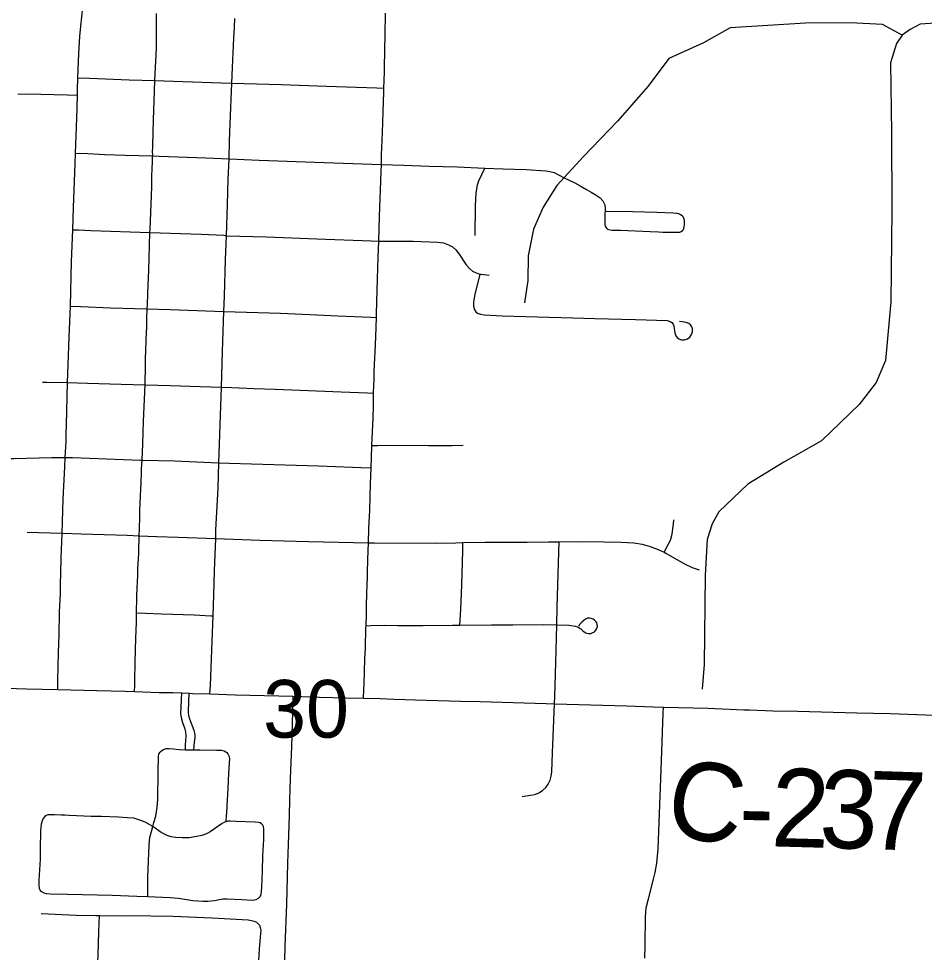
# Model space of a CAD drawing. Extents: x -59 to 43, y 0 to 22.
# Drawn here: x 25.512 to 26.169, y 16.594 to 17.272 of the extents above; entities that cross this region are included whole.
import ezdxf

# ---------------------------------------------------------------- set-up
doc = ezdxf.new("R2010")
doc.units = 0
for name, color, linetype in [('GM_X_City_Street', 7, 'Continuous'), ('GM_X_County_Road', 7, 'Continuous'), ('GM_X_County_Road_Text', 7, 'Continuous'), ('GM_X_Minor_River', 7, 'Continuous'), ('GM_X_Section_Text', 7, 'Continuous')]:
    doc.layers.add(name, color=color, linetype=linetype)

msp = doc.modelspace()

# ---------------------------------------------------------------- linework, layer by layer
at = {"layer": 'GM_X_City_Street'}
msp.add_line((25.63317, 16.74104), (25.63944, 16.74115), dxfattribs=at)
for points in [[(25.59632, 16.78345), (25.59641, 16.78792), (25.59649, 16.79187), (25.59673, 16.80396), (25.59705, 16.81375), (25.59719, 16.82198), (25.59771, 16.83378), (25.59776, 16.83691), (25.59772, 16.83937), (25.59772, 16.84054), (25.59772, 16.84306), (25.59777, 16.84429), (25.59787, 16.84799), (25.59805, 16.85414), (25.59819, 16.85721), (25.59849, 16.86457), (25.59862, 16.86644), (25.59861, 16.86763), (25.59877, 16.87243), (25.59887, 16.87656), (25.59916, 16.87988), (25.59933, 16.88358), (25.59947, 16.88863), (25.59954, 16.89323), (25.59964, 16.89656), (25.59979, 16.90185), (25.59982, 16.90251), (25.60003, 16.90923), (25.6002, 16.91477), (25.60035, 16.91968), (25.60074, 16.92585), (25.60086, 16.93018), (25.60102, 16.93513), (25.60128, 16.94196), (25.60141, 16.94443), (25.60157, 16.94878), (25.60172, 16.95138), (25.60241, 16.96328), (25.6029, 16.97973), (25.60395, 17.0062), (25.60404, 17.00827), (25.60428, 17.01823), (25.60436, 17.02588), (25.60443, 17.03016), (25.60477, 17.0392), (25.60501, 17.04347), (25.60515, 17.04853), (25.60525, 17.05162), (25.60532, 17.05407), (25.60551, 17.06136), (25.6056, 17.06459), (25.60615, 17.07868), (25.60663, 17.08921), (25.60746, 17.11679), (25.60753, 17.11914), (25.60801, 17.13115), (25.60875, 17.14983), (25.60891, 17.15789), (25.60907, 17.16274), (25.60923, 17.16825), (25.60944, 17.17231), (25.60948, 17.17298), (25.60943, 17.17545), (25.60947, 17.17837), (25.60953, 17.18241), (25.60973, 17.18654), (25.60985, 17.18956), (25.61036, 17.20626), (25.61054, 17.21183), (25.61114, 17.22693), (25.61216, 17.2505), (25.61218, 17.25585), (25.61231, 17.27567)], [(25.65096, 16.78173), (25.65133, 16.78808), (25.65171, 16.79422), (25.65274, 16.81992), (25.65339, 16.83837), (25.65393, 16.85337), (25.65445, 16.87112), (25.65542, 16.89462), (25.65542, 16.90056), (25.6569, 16.93123), (25.65738, 16.94953), (25.65934, 17.00445), (25.66006, 17.03042), (25.66104, 17.05937), (25.66153, 17.0705), (25.66226, 17.09722), (25.663, 17.11428), (25.66373, 17.13704), (25.66422, 17.1551), (25.66495, 17.17019), (25.6651, 17.18314), (25.66581, 17.19556), (25.66691, 17.22511), (25.6674, 17.23648), (25.66837, 17.25776), (25.66886, 17.26567), (25.66911, 17.27211)], [(25.55517, 17.22901), (25.56372, 17.22868), (25.59245, 17.22754), (25.61114, 17.22693), (25.6313, 17.22627), (25.65908, 17.22538), (25.66691, 17.22511), (25.70271, 17.22406), (25.73567, 17.22291), (25.75744, 17.22217), (25.77204, 17.22169), (25.7773, 17.22151)], [(25.51156, 17.21748), (25.52833, 17.21708), (25.54762, 17.21666), (25.55487, 17.2165)], [(25.55353, 17.1744), (25.56231, 17.17397), (25.57466, 17.17336), (25.58956, 17.17287), (25.60944, 17.17231), (25.61415, 17.17218), (25.64806, 17.17089), (25.66495, 17.17019), (25.68672, 17.16921), (25.73396, 17.1675), (25.77544, 17.1661), (25.79185, 17.16555), (25.81016, 17.16481), (25.83044, 17.16432), (25.85048, 17.16334)], [(25.84352, 17.11441), (25.8438, 17.13597), (25.84436, 17.14518), (25.84526, 17.15127), (25.84613, 17.15424), (25.85048, 17.16334)], [(25.85048, 17.16334), (25.86384, 17.16286), (25.88041, 17.16237), (25.89471, 17.16153), (25.89777, 17.16109), (25.90087, 17.16024), (25.90812, 17.15644), (25.91578, 17.15273), (25.91975, 17.15051), (25.92438, 17.14803), (25.92766, 17.14606), (25.93063, 17.14433), (25.93418, 17.1419), (25.93608, 17.13964), (25.93756, 17.13691), (25.93781, 17.13419), (25.93756, 17.129), (25.93758, 17.12413), (25.93774, 17.12247), (25.93794, 17.12128), (25.93831, 17.12054), (25.93885, 17.11983), (25.93964, 17.11918), (25.94059, 17.11877), (25.9415, 17.11853), (25.94304, 17.11836), (25.94909, 17.11832), (25.97054, 17.11742), (25.97655, 17.11716), (25.97971, 17.11706), (25.98585, 17.11694), (25.99001, 17.1169), (25.99135, 17.11693), (25.99197, 17.11701), (25.99305, 17.11738), (25.994, 17.1181), (25.99462, 17.11894), (25.99491, 17.11954), (25.99524, 17.12078), (25.99545, 17.12232), (25.99556, 17.12384), (25.99549, 17.12528), (25.99524, 17.12643), (25.99478, 17.1275), (25.99439, 17.12803), (25.99396, 17.12853), (25.99303, 17.12927), (25.99251, 17.12964), (25.99181, 17.13003), (25.99038, 17.13045), (25.98965, 17.13053), (25.98712, 17.13068), (25.97541, 17.13124), (25.9576, 17.13173), (25.93849, 17.13204)], [(25.55146, 17.11873), (25.55541, 17.11857), (25.5647, 17.11819), (25.60746, 17.11679), (25.64457, 17.11558), (25.66112, 17.11482), (25.663, 17.11428), (25.69218, 17.11355), (25.72857, 17.11219), (25.76813, 17.11062), (25.77356, 17.1104)], [(25.77356, 17.1104), (25.79858, 17.11035), (25.81608, 17.10977), (25.82051, 17.10909), (25.82422, 17.10785), (25.82706, 17.10621), (25.82951, 17.10403), (25.83191, 17.10097), (25.83698, 17.09316), (25.83934, 17.09047), (25.84165, 17.08868), (25.84425, 17.08734), (25.84699, 17.08655), (25.84766, 17.08635), (25.85187, 17.08586), (25.85373, 17.08577)], [(25.84699, 17.08655), (25.84537, 17.08043), (25.84316, 17.07205), (25.84223, 17.06604), (25.84228, 17.06315), (25.8429, 17.06101), (25.8441, 17.05919), (25.84529, 17.05816), (25.84731, 17.05735), (25.85012, 17.05703), (25.86312, 17.05632), (25.9144, 17.05481), (25.93039, 17.05425), (25.95991, 17.05355), (25.98293, 17.05273), (25.98497, 17.05215), (25.98624, 17.05135), (25.98723, 17.05015), (25.98776, 17.04875), (25.98833, 17.04378), (25.98907, 17.04171), (25.99002, 17.04042), (25.99127, 17.03945), (25.9933, 17.03877), (25.99547, 17.03879), (25.99751, 17.03951), (25.99928, 17.04083), (26.00056, 17.0426), (26.00125, 17.04467), (26.00124, 17.04682), (26.00072, 17.04831), (25.99978, 17.04961), (25.99853, 17.0506), (25.99658, 17.05148), (25.99372, 17.05195), (25.99191, 17.05204)], [(25.54972, 17.06322), (25.5574, 17.06293), (25.57896, 17.06211), (25.60551, 17.06136), (25.62204, 17.06088), (25.66104, 17.05937), (25.70216, 17.05816), (25.72358, 17.05722), (25.74391, 17.05619), (25.7679, 17.05521), (25.77185, 17.05505)], [(25.52957, 17.0081), (25.53267, 17.00804), (25.54765, 17.0077), (25.56212, 17.00738), (25.58661, 17.00664), (25.60395, 17.0062), (25.62237, 17.00574), (25.64401, 17.0049), (25.65934, 17.00445), (25.66701, 17.00421), (25.68302, 17.00342), (25.69831, 17.0029), (25.71648, 17.00225), (25.74616, 17.00103), (25.76546, 17.00029), (25.76984, 17.00013)], [(25.76861, 16.96197), (25.77292, 16.96207), (25.77858, 16.9622), (25.8096, 16.96209), (25.81868, 16.96206), (25.82682, 16.96198), (25.83474, 16.96223)], [(25.47792, 16.95274), (25.48704, 16.95273), (25.50886, 16.95261), (25.5361, 16.95325), (25.54601, 16.95348)], [(25.54601, 16.95348), (25.55126, 16.95328), (25.60052, 16.9514), (25.60172, 16.95138), (25.6252, 16.95088), (25.64671, 16.94991), (25.65738, 16.94953), (25.66505, 16.94931), (25.72972, 16.94729), (25.7544, 16.94634), (25.76057, 16.94615), (25.76804, 16.94592)], [(25.9806, 16.88462), (25.98343, 16.88982), (25.98517, 16.89328), (25.98615, 16.89674), (25.98664, 16.89946), (25.98689, 16.90194), (25.98738, 16.90491), (25.98763, 16.90814)], [(25.51844, 16.89922), (25.54379, 16.89851), (25.55768, 16.89802), (25.57421, 16.89745), (25.59089, 16.89687), (25.59964, 16.89656), (25.61226, 16.89612), (25.62795, 16.89557), (25.65542, 16.89462), (25.68734, 16.89339), (25.72257, 16.89231), (25.76605, 16.89148)], [(25.76605, 16.89148), (25.77045, 16.89145), (25.81448, 16.89123), (25.82944, 16.89149), (25.83457, 16.89156), (25.85051, 16.89178), (25.88123, 16.89197), (25.89672, 16.89216), (25.90459, 16.89226), (25.91843, 16.89242), (25.93703, 16.89205), (25.94941, 16.89183), (25.95865, 16.89137), (25.96469, 16.89044), (25.97059, 16.88882), (25.97634, 16.88666), (25.9806, 16.88462), (25.98187, 16.88402), (25.98982, 16.87926), (25.99537, 16.87608), (26.00112, 16.87347), (26.00597, 16.87183)], [(25.83232, 16.83162), (25.83281, 16.83904), (25.8333, 16.84857), (25.8339, 16.861), (25.83445, 16.88588), (25.83457, 16.89156)], [(25.90119, 16.77461), (25.90136, 16.77995), (25.90209, 16.8042), (25.90275, 16.83189), (25.90306, 16.84464), (25.90435, 16.88472), (25.90459, 16.89226)], [(25.59772, 16.84054), (25.604, 16.84032), (25.61582, 16.83989), (25.63963, 16.83914), (25.65174, 16.83846), (25.65339, 16.83837)], [(25.76433, 16.83126), (25.76776, 16.83134), (25.7774, 16.8316), (25.7873, 16.83135), (25.80577, 16.83143), (25.82714, 16.83165), (25.83232, 16.83162), (25.85526, 16.83183), (25.87091, 16.83187), (25.89286, 16.83214), (25.90275, 16.83189), (25.91156, 16.83168), (25.91462, 16.83128), (25.91642, 16.83097), (25.91759, 16.83052), (25.91905, 16.82978), (25.92025, 16.82888), (25.92177, 16.82745), (25.92328, 16.82633), (25.92435, 16.82579), (25.92582, 16.82548), (25.92736, 16.82563), (25.92855, 16.82597), (25.93007, 16.82687), (25.93118, 16.82798), (25.93188, 16.82934), (25.93221, 16.83082), (25.93204, 16.83221), (25.93172, 16.83333), (25.93114, 16.83439), (25.93007, 16.83534), (25.92912, 16.83603), (25.92781, 16.83657), (25.92645, 16.83677), (25.92505, 16.83665), (25.92369, 16.83608), (25.92233, 16.83509), (25.92085, 16.83377), (25.91949, 16.83226), (25.91843, 16.83056)], [(25.63317, 16.74104), (25.63337, 16.74448), (25.63378, 16.7512), (25.63356, 16.75428), (25.63313, 16.75608), (25.63147, 16.76073), (25.63036, 16.76427), (25.63005, 16.76609), (25.62999, 16.76732), (25.63035, 16.77723), (25.63054, 16.78244)], [(25.63944, 16.74115), (25.63967, 16.74387), (25.63991, 16.74683), (25.64026, 16.7497), (25.64022, 16.75218), (25.63951, 16.75519), (25.63638, 16.76333), (25.63579, 16.76574), (25.63546, 16.76882), (25.6357, 16.77632), (25.63589, 16.78221)], [(25.70526, 16.58858), (25.70556, 16.59852), (25.70671, 16.6291), (25.70764, 16.65878), (25.70802, 16.67245), (25.70874, 16.69358), (25.70903, 16.70476), (25.7093, 16.71251), (25.70955, 16.72028), (25.7102, 16.73767), (25.71038, 16.74325), (25.71142, 16.77728), (25.7115, 16.77999)], [(25.87754, 16.70736), (25.88378, 16.70816), (25.88684, 16.70882), (25.88977, 16.70993), (25.89243, 16.71159), (25.89471, 16.71374), (25.89653, 16.71629), (25.89787, 16.71912), (25.89871, 16.72214), (25.8991, 16.72525), (25.89965, 16.73889), (25.90119, 16.77461)], [(25.96675, 16.59), (25.96699, 16.59916), (25.96723, 16.61993), (25.96772, 16.62637), (25.9692, 16.63305), (25.97283, 16.64728), (25.97414, 16.6521), (25.97537, 16.65878), (25.97636, 16.66917), (25.97709, 16.68846), (25.9788, 16.73324), (25.98003, 16.76786), (25.98018, 16.77218)], [(25.60952, 16.6855), (25.61034, 16.68848), (25.61172, 16.69288), (25.61283, 16.6993), (25.61332, 16.70534), (25.61333, 16.7246), (25.61365, 16.73652), (25.61393, 16.73789), (25.61454, 16.73922), (25.61495, 16.73981), (25.61608, 16.74075), (25.61734, 16.74143), (25.61934, 16.742), (25.62137, 16.74215), (25.62461, 16.74184), (25.62869, 16.74128), (25.63317, 16.74104)], [(25.63944, 16.74115), (25.64368, 16.74122), (25.6561, 16.74093), (25.65934, 16.74091), (25.66137, 16.74045), (25.66264, 16.73973), (25.66319, 16.7393), (25.6641, 16.73816), (25.66472, 16.73686), (25.66512, 16.73481), (25.66492, 16.73152), (25.66459, 16.72426), (25.66411, 16.71316), (25.66335, 16.70053), (25.66302, 16.69493), (25.66291, 16.6937), (25.66249, 16.68892)], [(25.60952, 16.6855), (25.60395, 16.68856), (25.59938, 16.6904), (25.59568, 16.69152), (25.59124, 16.69188), (25.58478, 16.69224), (25.57236, 16.6927), (25.56489, 16.69282), (25.54875, 16.69349), (25.54566, 16.6936), (25.54325, 16.69362), (25.53829, 16.69385), (25.53455, 16.69405), (25.53334, 16.69388), (25.5322, 16.69344), (25.53119, 16.69275), (25.52999, 16.69134), (25.52916, 16.68967), (25.52856, 16.68726), (25.52812, 16.6823), (25.5279, 16.66926), (25.5277, 16.66181), (25.52692, 16.64629), (25.52678, 16.64255), (25.52708, 16.64071), (25.52791, 16.63908), (25.52879, 16.63822), (25.53037, 16.6373), (25.53216, 16.63681), (25.53527, 16.63662), (25.54771, 16.63644), (25.58, 16.63559), (25.59801, 16.635), (25.60598, 16.63468)], [(25.60598, 16.63468), (25.62221, 16.63402), (25.62803, 16.63354), (25.63269, 16.63285), (25.63852, 16.63182), (25.64222, 16.63145), (25.64592, 16.63133), (25.6495, 16.63133), (25.65431, 16.63183), (25.66043, 16.63286), (25.66353, 16.63299), (25.67408, 16.63259), (25.68217, 16.63207), (25.6834, 16.63216), (25.6846, 16.63246), (25.68619, 16.63336), (25.68739, 16.63476), (25.68816, 16.63645), (25.68855, 16.63828), (25.68862, 16.64138), (25.6891, 16.65306), (25.68949, 16.66434), (25.69021, 16.67612), (25.69015, 16.6836), (25.68986, 16.68544), (25.68933, 16.68653), (25.68852, 16.68742), (25.68749, 16.68806), (25.68632, 16.68844), (25.68383, 16.68868), (25.67016, 16.68916), (25.66582, 16.68943), (25.66403, 16.68932), (25.66249, 16.68892)], [(25.66249, 16.68892), (25.66169, 16.68871), (25.65997, 16.68765), (25.65129, 16.68162), (25.64854, 16.68019), (25.64502, 16.679), (25.64017, 16.67788), (25.63586, 16.67732), (25.63089, 16.67721), (25.62593, 16.67754), (25.62288, 16.67806), (25.61991, 16.679), (25.61555, 16.68116), (25.60952, 16.6855)], [(25.60598, 16.63468), (25.60594, 16.6402), (25.60588, 16.64887), (25.60684, 16.67187), (25.60742, 16.67749), (25.60852, 16.6819), (25.60952, 16.6855)], [(25.52855, 16.62223), (25.554, 16.62118), (25.56829, 16.62082), (25.5708, 16.6208)], [(25.56774, 16.54259), (25.56803, 16.54862), (25.56874, 16.56348), (25.56993, 16.5926), (25.57031, 16.60872), (25.57059, 16.61553), (25.5708, 16.6208)], [(25.5708, 16.6208), (25.58692, 16.62068), (25.5925, 16.62089), (25.62419, 16.62038), (25.65274, 16.61911), (25.67882, 16.61775), (25.68128, 16.61734), (25.68306, 16.61678), (25.68471, 16.61593), (25.68613, 16.61473), (25.68688, 16.61376), (25.68759, 16.61206), (25.68788, 16.61022), (25.68782, 16.60772), (25.68672, 16.59658), (25.6862, 16.5879), (25.68622, 16.58105), (25.68604, 16.5764)]]:
    msp.add_lwpolyline(points, dxfattribs=at)
at = {"layer": 'GM_X_County_Road'}
msp.add_line((25.98018, 16.77218), (26.01264, 16.77128), dxfattribs=at)
for points in [[(25.55517, 17.22901), (25.55588, 17.24667), (25.55667, 17.25905), (25.55728, 17.26643), (25.55885, 17.28), (25.55947, 17.28394)], [(25.7773, 17.22151), (25.7775, 17.22717), (25.77768, 17.23333), (25.77771, 17.23583), (25.77791, 17.24948), (25.77826, 17.26004), (25.77854, 17.27585)], [(25.55487, 17.2165), (25.5549, 17.21995), (25.55517, 17.22901)], [(25.55353, 17.1744), (25.55419, 17.19327), (25.55478, 17.20692), (25.55487, 17.2165)], [(25.77544, 17.1661), (25.77564, 17.17304), (25.7762, 17.18899), (25.77686, 17.20443), (25.77721, 17.21858), (25.7773, 17.22151)], [(25.55146, 17.11873), (25.55201, 17.13486), (25.55325, 17.16654), (25.55353, 17.1744)], [(25.77356, 17.1104), (25.77417, 17.1284), (25.77529, 17.16066), (25.77544, 17.1661)], [(25.54972, 17.06322), (25.55067, 17.09571), (25.55146, 17.11873)], [(25.77185, 17.05505), (25.77194, 17.05767), (25.77274, 17.08312), (25.77316, 17.09863), (25.77356, 17.1104)], [(25.54765, 17.0077), (25.54809, 17.02086), (25.54895, 17.04062), (25.54972, 17.06322)], [(25.76984, 17.00013), (25.76985, 17.00078), (25.76997, 17.00522), (25.7701, 17.01028), (25.77021, 17.0151), (25.77046, 17.02102), (25.77084, 17.02986), (25.7714, 17.04094), (25.77185, 17.05505)], [(25.54601, 16.95348), (25.54663, 16.96505), (25.54679, 16.97089), (25.54687, 16.97681), (25.5473, 16.99729), (25.54765, 17.0077)], [(25.76861, 16.96197), (25.76937, 16.9819), (25.76961, 16.99116), (25.76984, 17.00013)], [(25.76804, 16.94592), (25.76827, 16.95303), (25.76861, 16.96197)], [(25.54379, 16.89851), (25.54455, 16.92316), (25.54565, 16.94663), (25.54601, 16.95348)], [(25.76605, 16.89148), (25.76644, 16.90171), (25.76705, 16.91504), (25.76766, 16.9344), (25.76804, 16.94592)], [(25.54051, 16.78492), (25.54062, 16.79166), (25.54078, 16.80187), (25.5411, 16.81149), (25.54151, 16.82456), (25.54191, 16.84102), (25.54248, 16.85475), (25.54264, 16.86166), (25.54281, 16.86925), (25.54312, 16.88041), (25.54354, 16.89214), (25.54379, 16.89851)], [(25.76433, 16.83126), (25.76475, 16.83915), (25.76468, 16.8456), (25.76498, 16.85458), (25.76519, 16.86143), (25.76535, 16.86605), (25.76544, 16.86991), (25.76572, 16.87913), (25.76583, 16.88567), (25.76605, 16.89148)], [(25.76259, 16.77861), (25.7628, 16.785), (25.76291, 16.78882), (25.76352, 16.8072), (25.76389, 16.81522), (25.76426, 16.82978), (25.76433, 16.83126)], [(25.4237, 16.7885), (25.44088, 16.78789), (25.44895, 16.78764), (25.46697, 16.78704), (25.51792, 16.78549), (25.54051, 16.78492)], [(25.54051, 16.78492), (25.56887, 16.7842), (25.58939, 16.78369), (25.59632, 16.78345)], [(25.59632, 16.78345), (25.61423, 16.78285), (25.62417, 16.78271), (25.63054, 16.78244)], [(25.63054, 16.78244), (25.63589, 16.78221), (25.63846, 16.7821), (25.65096, 16.78173)], [(25.65096, 16.78173), (25.66952, 16.78117), (25.7115, 16.77999)], [(25.7115, 16.77999), (25.73042, 16.77947), (25.74968, 16.77894), (25.76259, 16.77861)], [(25.76259, 16.77861), (25.77454, 16.77832), (25.78448, 16.77799), (25.80809, 16.7773), (25.83294, 16.77656), (25.84723, 16.7763), (25.89508, 16.77474), (25.90119, 16.77461)], [(25.90119, 16.77461), (25.91, 16.77441), (25.92739, 16.77389), (25.95351, 16.77314), (25.97276, 16.77238), (25.98018, 16.77218)], [(26.01264, 16.77128), (26.01741, 16.77108), (26.0385, 16.77021), (26.04251, 16.77009)], [(26.04251, 16.77009), (26.05959, 16.76957), (26.07759, 16.76926), (26.12041, 16.768), (26.14464, 16.76755), (26.17691, 16.76626), (26.18278, 16.76603)]]:
    msp.add_lwpolyline(points, dxfattribs=at)
at = {"layer": 'GM_X_Minor_River'}
for points in [[(26.15347, 17.26001), (26.13907, 17.26765), (26.11593, 17.26886), (26.0833, 17.26857), (26.02865, 17.26531), (26.00927, 17.25435), (25.98419, 17.24303), (25.96896, 17.22294), (25.94687, 17.19755), (25.92213, 17.17178), (25.90272, 17.15094), (25.8928, 17.13502), (25.88592, 17.11908), (25.88207, 17.09972), (25.88164, 17.08186), (25.87931, 17.06553)], [(26.1774, 17.26868), (26.1664, 17.26795), (26.15917, 17.26417), (26.15347, 17.26001), (26.14928, 17.25394), (26.14506, 17.2399), (26.14567, 17.18899), (26.14588, 17.13314), (26.14529, 17.06628), (26.14137, 17.02374), (26.13449, 17.0078), (26.1223, 16.99188), (26.0949, 16.96537), (26.06754, 16.94987), (26.04131, 16.93399), (26.02038, 16.91391), (26.01542, 16.90519), (26.01197, 16.8938), (26.01038, 16.86797), (26.0098, 16.80301), (26.00823, 16.78516)]]:
    msp.add_lwpolyline(points, dxfattribs=at)

# ---------------------------------------------------------------- texts
at = {"layer": 'GM_X_County_Road_Text'}
for s, rotation, p in [('C', 350.76096, (25.97991, 16.67989)), ('2', 358.41782, (26.05783, 16.67111)), ('3', 358.40221, (26.09281, 16.67014)), ('7', 358.12622, (26.12773, 16.66917)), ('-', 358.76264, (26.03459, 16.67161))]:
    msp.add_text(s, height=0.05682, rotation=rotation, dxfattribs=at).set_placement(p)
at = {"layer": 'GM_X_Section_Text'}
msp.add_text('30', height=0.041856, rotation=0.00001, dxfattribs=at).set_placement((25.68964, 16.75))

doc.saveas('drawing.dxf')
